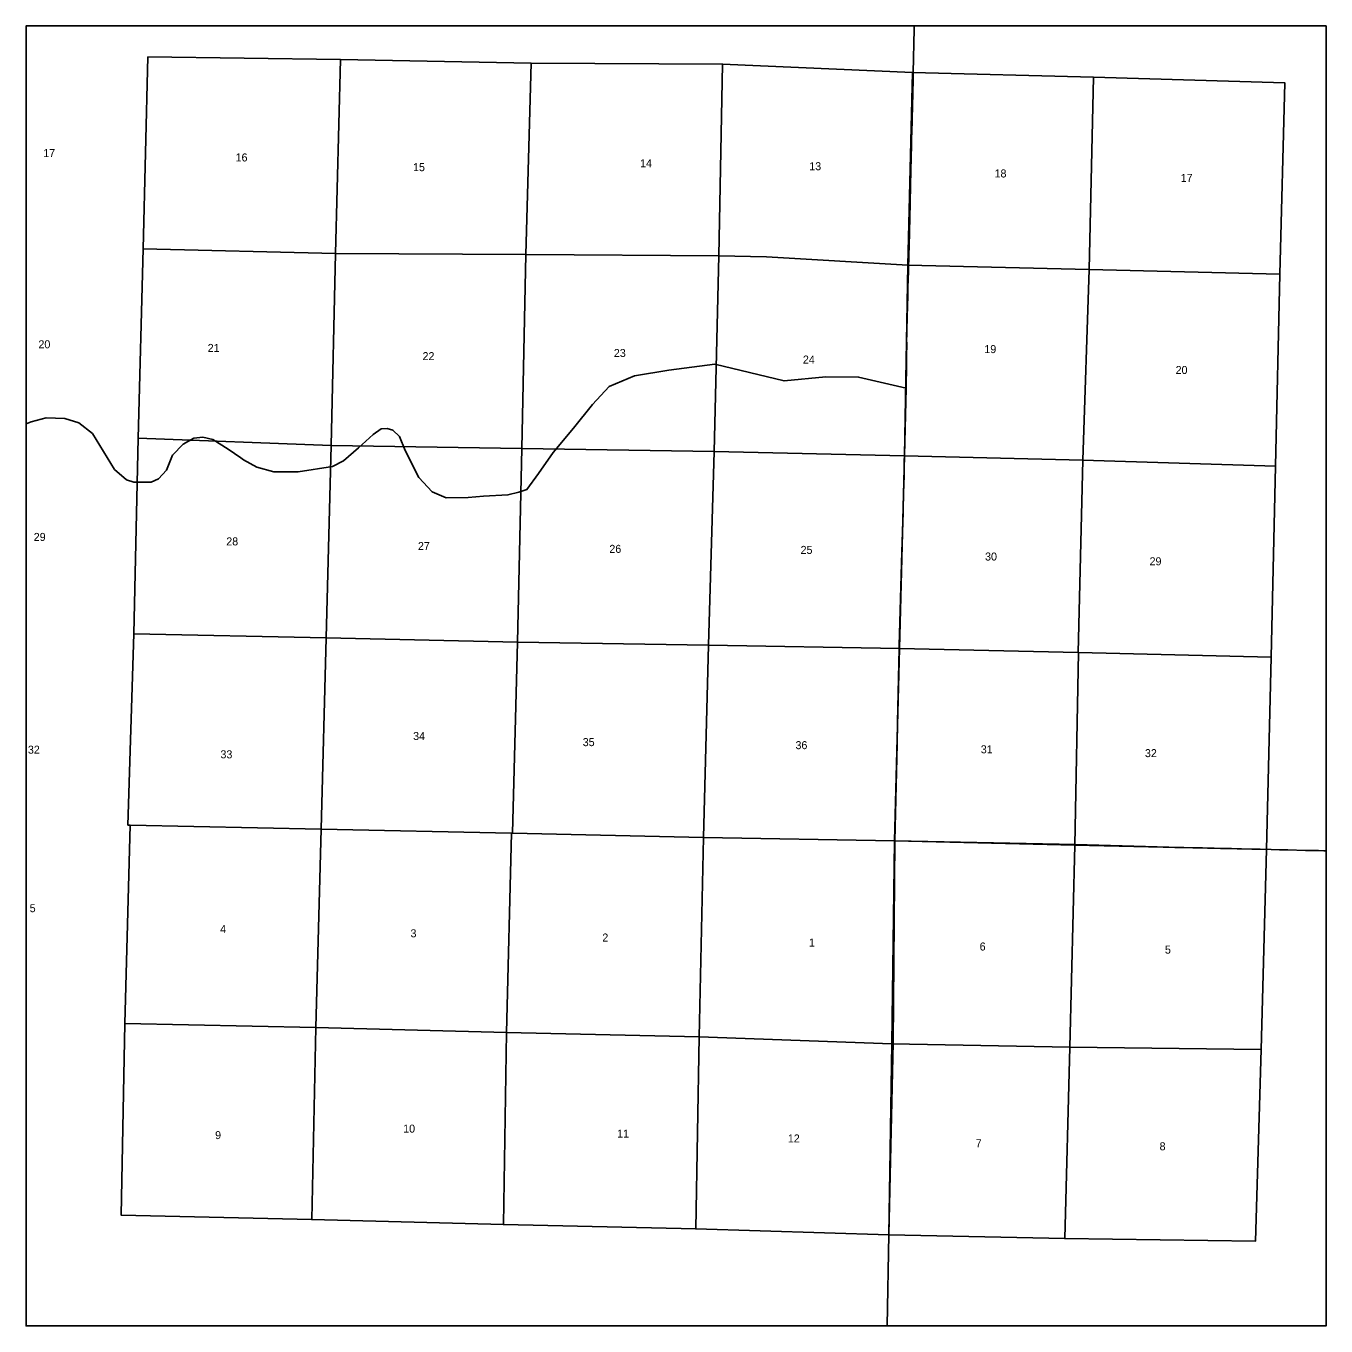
# Model space of a CAD drawing. Extents: x -483 to 680, y 0 to 440.
# Drawn here: x -395.42 to -388.62, y 271.57 to 278.37 of the extents above; entities that cross this region are included whole.
import ezdxf

# ---------------------------------------------------------------- set-up
doc = ezdxf.new("R2010")
doc.units = 0
doc.layers.add('GM_X_Section', color=7, linetype='Continuous')
doc.layers.add('GM_X_Section_Text', color=7, linetype='Continuous')

msp = doc.modelspace()

# ---------------------------------------------------------------- linework, layer by layer
at = {"layer": 'GM_X_Section'}
for points in [[(-394.782, 278.2055), (-393.775, 278.1914), (-393.8002, 277.1762), (-394.8063, 277.2013)], [(-393.775, 278.1914), (-392.7782, 278.173), (-392.8051, 277.1722), (-393.8002, 277.1762)], [(-392.7782, 278.173), (-391.7758, 278.1679), (-391.7952, 277.1651), (-392.8051, 277.1722)], [(-391.7758, 278.1679), (-390.7819, 278.1232), (-390.8079, 277.116), (-391.546, 277.1593), (-391.7952, 277.1651)], [(-390.7819, 278.1232), (-389.8362, 278.0985), (-389.8594, 277.0939), (-390.8079, 277.116)], [(-389.8362, 278.0985), (-388.8351, 278.0689), (-388.8613, 277.0689), (-389.8594, 277.0939)], [(-394.8063, 277.2013), (-393.8002, 277.1762), (-393.8233, 276.1724), (-394.8329, 276.2104)], [(-393.8002, 277.1762), (-392.8051, 277.1722), (-392.8261, 276.157), (-393.8233, 276.1724)], [(-392.8051, 277.1722), (-391.7952, 277.1651), (-391.8203, 276.1412), (-392.8261, 276.157)], [(-391.7952, 277.1651), (-391.546, 277.1593), (-390.8079, 277.116), (-390.8252, 276.1185), (-391.8203, 276.1412)], [(-390.8079, 277.116), (-389.8594, 277.0939), (-389.8919, 276.0952), (-390.8252, 276.1185)], [(-389.8594, 277.0939), (-388.8613, 277.0689), (-388.8841, 276.0644), (-389.8919, 276.0952)], [(-394.8329, 276.2104), (-393.8233, 276.1724), (-393.8502, 275.1667), (-394.8563, 275.188)], [(-393.8233, 276.1724), (-392.8261, 276.157), (-392.8487, 275.1444), (-393.8502, 275.1667)], [(-392.8261, 276.157), (-391.8203, 276.1412), (-391.8493, 275.1284), (-392.8487, 275.1444)], [(-391.8203, 276.1412), (-390.8252, 276.1185), (-390.8511, 275.111), (-391.8493, 275.1284)], [(-390.8252, 276.1185), (-389.8919, 276.0952), (-389.9167, 275.0896), (-390.8511, 275.111)], [(-389.8919, 276.0952), (-388.8841, 276.0644), (-388.9069, 275.0647), (-389.914, 275.0895), (-389.9167, 275.0896)], [(-394.8563, 275.188), (-393.8502, 275.1667), (-393.8766, 274.1663), (-394.8748, 274.187), (-394.8869, 274.1873)], [(-393.8502, 275.1667), (-392.8487, 275.1444), (-392.8754, 274.1452), (-392.8811, 274.1449), (-393.8766, 274.1663)], [(-392.8487, 275.1444), (-391.8493, 275.1284), (-391.8756, 274.1216), (-392.8754, 274.1452)], [(-391.8493, 275.1284), (-390.8511, 275.111), (-390.8762, 274.1046), (-391.8756, 274.1216)], [(-390.8511, 275.111), (-389.9167, 275.0896), (-389.914, 275.0895), (-389.9342, 274.0826), (-390.8762, 274.1046)], [(-389.914, 275.0895), (-388.9069, 275.0647), (-388.9304, 274.0602), (-389.9342, 274.0826)], [(-394.8748, 274.187), (-393.8766, 274.1663), (-393.9036, 273.1275), (-394.9025, 273.1486)], [(-393.8766, 274.1663), (-392.8811, 274.1449), (-392.9059, 273.1018), (-393.9036, 273.1275)], [(-392.8811, 274.1449), (-392.8754, 274.1452), (-391.8756, 274.1216), (-391.8981, 273.0802), (-392.9059, 273.1018)], [(-391.8756, 274.1216), (-390.8762, 274.1046), (-390.8908, 273.0436), (-391.8981, 273.0802)], [(-390.8762, 274.1046), (-389.9342, 274.0826), (-389.9605, 273.0249), (-390.8908, 273.0436)], [(-388.9304, 274.0602), (-388.9595, 273.0134), (-389.9605, 273.0249), (-389.9342, 274.0826)], [(-393.9036, 273.1275), (-393.9252, 272.1233), (-394.9222, 272.1474), (-394.9025, 273.1486)], [(-392.9059, 273.1018), (-392.9223, 272.0975), (-393.9252, 272.1233), (-393.9036, 273.1275)], [(-392.9059, 273.1018), (-391.8981, 273.0802), (-391.9168, 272.0748), (-392.9223, 272.0975)], [(-391.8981, 273.0802), (-390.8908, 273.0436), (-390.9067, 272.0446), (-391.9168, 272.0748)], [(-390.8908, 273.0436), (-389.9605, 273.0249), (-389.9863, 272.0242), (-390.9067, 272.0446)], [(-389.9605, 273.0249), (-388.9595, 273.0134), (-388.9881, 272.0109), (-389.9863, 272.0242)]]:
    msp.add_lwpolyline(points, close=True, dxfattribs=at)
at = {"layer": 'GM_X_Section_Text'}
for points in [[(-390.7732, 278.367), (-395.4198, 278.367), (-395.4198, 276.2868), (-395.3923, 276.2971), (-395.3141, 276.3178), (-395.2175, 276.3133), (-395.144, 276.2915), (-395.0715, 276.2352), (-394.9564, 276.0479), (-394.8942, 275.9939), (-394.8563, 275.9801), (-394.7649, 275.981), (-394.727, 275.9983), (-394.6845, 276.0443), (-394.6535, 276.1214), (-394.5984, 276.1789), (-394.542, 276.2112), (-394.4949, 276.2158), (-394.442, 276.2032), (-394.3615, 276.1527), (-394.2965, 276.1073), (-394.282, 276.0973), (-394.212, 276.0585), (-394.1234, 276.0345), (-393.9958, 276.0357), (-393.8165, 276.0635), (-393.759, 276.0923), (-393.6802, 276.1604), (-393.6044, 276.2294), (-393.5619, 276.2605), (-393.5309, 276.2617), (-393.501, 276.2525), (-393.4653, 276.2204), (-393.4365, 276.1468), (-393.3651, 276.0054), (-393.2949, 275.9307), (-393.2213, 275.8986), (-393.1075, 275.8999), (-393.0259, 275.908), (-392.8994, 275.9138), (-392.8412, 275.9278), (-392.7994, 275.9427), (-392.7385, 276.0267), (-392.6627, 276.136), (-392.5555, 276.263), (-392.4567, 276.3873), (-392.3694, 276.4817), (-392.2361, 276.537), (-392.0579, 276.5659), (-391.8168, 276.5986), (-391.4548, 276.5106), (-391.2363, 276.5326), (-391.065, 276.5304), (-390.8157, 276.4729), (-390.8138, 276.597), (-390.8138, 276.6176), (-390.8135, 276.643), (-390.8133, 276.6622), (-390.8131, 276.6815), (-390.8131, 276.6861), (-390.8131, 276.7038), (-390.8133, 276.7243), (-390.813, 276.751), (-390.8126, 276.7696), (-390.8121, 276.7895), (-390.8109, 276.828), (-390.8105, 276.8382), (-390.8099, 276.8528), (-390.8088, 276.8945), (-390.8081, 276.9181), (-390.8076, 276.9379), (-390.8072, 276.9559), (-390.807, 276.9678), (-390.8068, 276.9781), (-390.8063, 276.9979), (-390.805, 277.0438), (-390.8049, 277.049), (-390.8043, 277.0736), (-390.804, 277.0851), (-390.8034, 277.1037), (-390.8031, 277.1176), (-390.8025, 277.1418), (-390.8021, 277.1582), (-390.802, 277.1586), (-390.8014, 277.1803), (-390.8005, 277.2064), (-390.7997, 277.2368), (-390.7988, 277.2691), (-390.7978, 277.3131), (-390.7973, 277.3423), (-390.7974, 277.3556), (-390.7969, 277.3765), (-390.7958, 277.4295), (-390.7958, 277.4306), (-390.7951, 277.4511), (-390.7945, 277.4753), (-390.7939, 277.4995), (-390.7931, 277.5356), (-390.7928, 277.5592), (-390.7921, 277.5841), (-390.7913, 277.6114), (-390.7909, 277.6264), (-390.7902, 277.6624), (-390.7894, 277.6916), (-390.7884, 277.729), (-390.7876, 277.7714), (-390.7862, 277.8227), (-390.7849, 277.865), (-390.7843, 277.8845), (-390.7841, 277.8919), (-390.7839, 277.9016), (-390.7832, 277.9263), (-390.7829, 277.9356), (-390.7826, 277.958), (-390.7814, 278.0034), (-390.7808, 278.0265), (-390.7799, 278.0749), (-390.7789, 278.1213), (-390.7788, 278.1247), (-390.7771, 278.1975), (-390.7751, 278.2771), (-390.7737, 278.3492)], [(-388.6198, 274.0523), (-388.6198, 278.367), (-390.7732, 278.367), (-390.7737, 278.3492), (-390.7751, 278.2771), (-390.7771, 278.1975), (-390.7788, 278.1247), (-390.7789, 278.1213), (-390.7799, 278.0749), (-390.7808, 278.0265), (-390.7814, 278.0034), (-390.7826, 277.958), (-390.7829, 277.9356), (-390.7832, 277.9263), (-390.7839, 277.9016), (-390.7841, 277.8919), (-390.7843, 277.8845), (-390.7849, 277.865), (-390.7862, 277.8227), (-390.7876, 277.7714), (-390.7884, 277.729), (-390.7894, 277.6916), (-390.7902, 277.6624), (-390.7909, 277.6264), (-390.7913, 277.6114), (-390.7921, 277.5841), (-390.7928, 277.5592), (-390.7931, 277.5356), (-390.7939, 277.4995), (-390.7945, 277.4753), (-390.7951, 277.4511), (-390.7958, 277.4306), (-390.7958, 277.4295), (-390.7969, 277.3765), (-390.7974, 277.3556), (-390.7973, 277.3423), (-390.7978, 277.3131), (-390.7988, 277.2691), (-390.7997, 277.2368), (-390.8005, 277.2064), (-390.8014, 277.1803), (-390.802, 277.1586), (-390.8021, 277.1582), (-390.8025, 277.1418), (-390.8031, 277.1176), (-390.8034, 277.1037), (-390.804, 277.0851), (-390.8043, 277.0736), (-390.8049, 277.049), (-390.805, 277.0438), (-390.8063, 276.9979), (-390.8068, 276.9781), (-390.807, 276.9678), (-390.8072, 276.9559), (-390.8076, 276.9379), (-390.8081, 276.9181), (-390.8088, 276.8945), (-390.8099, 276.8528), (-390.8105, 276.8382), (-390.8109, 276.828), (-390.8121, 276.7895), (-390.8126, 276.7696), (-390.813, 276.751), (-390.8133, 276.7243), (-390.8131, 276.7038), (-390.8131, 276.6861), (-390.8131, 276.6815), (-390.8133, 276.6622), (-390.8135, 276.643), (-390.8138, 276.6176), (-390.8138, 276.597), (-390.8157, 276.4729), (-390.8249, 276.121), (-390.8256, 276.0925), (-390.826, 276.0764), (-390.8264, 276.0491), (-390.8269, 276.023), (-390.8271, 276.0159), (-390.8293, 275.9238), (-390.8301, 275.8925), (-390.8308, 275.8695), (-390.8321, 275.823), (-390.8379, 275.6172), (-390.8518, 275.1259), (-390.8518, 275.1249), (-390.8518, 275.11), (-390.861, 274.7231), (-390.8637, 274.6104), (-390.8757, 274.1044), (-389.9296, 274.0853), (-389.4417, 274.0723), (-389.4098, 274.0707), (-389.4043, 274.0706), (-389.3628, 274.0699), (-389.2994, 274.0685), (-389.2664, 274.0675), (-389.2043, 274.0664), (-389.1713, 274.0654), (-389.1378, 274.0645), (-389.1135, 274.0639), (-389.0619, 274.0627), (-388.965, 274.0607), (-388.9072, 274.059), (-388.8637, 274.0578), (-388.8195, 274.0569), (-388.7269, 274.0549), (-388.6585, 274.0534), (-388.6312, 274.0525)], [(-395.4198, 276.2868), (-395.4198, 271.567), (-390.915, 271.567), (-390.907, 272.0456), (-390.8845, 273.0503), (-390.8757, 274.1044), (-390.8637, 274.6104), (-390.861, 274.7231), (-390.8518, 275.11), (-390.8518, 275.1249), (-390.8518, 275.1259), (-390.8379, 275.6172), (-390.8321, 275.823), (-390.8308, 275.8695), (-390.8301, 275.8925), (-390.8293, 275.9238), (-390.8271, 276.0159), (-390.8269, 276.023), (-390.8264, 276.0491), (-390.826, 276.0764), (-390.8256, 276.0925), (-390.8249, 276.121), (-390.8157, 276.4729), (-391.065, 276.5304), (-391.2363, 276.5326), (-391.4548, 276.5106), (-391.8168, 276.5986), (-392.0579, 276.5659), (-392.2361, 276.537), (-392.3694, 276.4817), (-392.4567, 276.3873), (-392.5555, 276.263), (-392.6627, 276.136), (-392.7385, 276.0267), (-392.7994, 275.9427), (-392.8412, 275.9278), (-392.8994, 275.9138), (-393.0259, 275.908), (-393.1075, 275.8999), (-393.2213, 275.8986), (-393.2949, 275.9307), (-393.3651, 276.0054), (-393.4365, 276.1468), (-393.4653, 276.2204), (-393.501, 276.2525), (-393.5309, 276.2617), (-393.5619, 276.2605), (-393.6044, 276.2294), (-393.6802, 276.1604), (-393.759, 276.0923), (-393.8165, 276.0635), (-393.9958, 276.0357), (-394.1234, 276.0345), (-394.212, 276.0585), (-394.282, 276.0973), (-394.2965, 276.1073), (-394.3615, 276.1527), (-394.442, 276.2032), (-394.4949, 276.2158), (-394.542, 276.2112), (-394.5984, 276.1789), (-394.6535, 276.1214), (-394.6845, 276.0443), (-394.727, 275.9983), (-394.7649, 275.981), (-394.8563, 275.9801), (-394.8942, 275.9939), (-394.9564, 276.0479), (-395.0715, 276.2352), (-395.144, 276.2915), (-395.2175, 276.3133), (-395.3141, 276.3178), (-395.3923, 276.2971)], [(-390.915, 271.567), (-388.6198, 271.567), (-388.6198, 274.0523), (-388.6312, 274.0525), (-388.6585, 274.0534), (-388.7269, 274.0549), (-388.8195, 274.0569), (-388.8637, 274.0578), (-388.9072, 274.059), (-388.965, 274.0607), (-389.0619, 274.0627), (-389.1135, 274.0639), (-389.1378, 274.0645), (-389.1713, 274.0654), (-389.2043, 274.0664), (-389.2664, 274.0675), (-389.2994, 274.0685), (-389.3628, 274.0699), (-389.4043, 274.0706), (-389.4098, 274.0707), (-389.4417, 274.0723), (-389.9296, 274.0853), (-390.8757, 274.1044), (-390.8845, 273.0503), (-390.907, 272.0456)]]:
    msp.add_lwpolyline(points, close=True, dxfattribs=at)

# ---------------------------------------------------------------- texts
for s, height, p in [('17', 0.04186, (-395.3298, 277.6811)), ('16', 0.04186, (-394.3235, 277.6585)), ('15', 0.04186, (-393.3952, 277.6077)), ('14', 0.04186, (-392.2077, 277.6279)), ('13', 0.04186, (-391.3227, 277.6126)), ('18', 0.04186, (-390.3535, 277.5747)), ('17', 0.04186, (-389.3798, 277.5515)), ('20', 0.04186, (-395.3548, 276.681)), ('21', 0.04186, (-394.4694, 276.6621)), ('19', 0.04186, (-390.4069, 276.656)), ('22', 0.04186, (-393.3456, 276.6192)), ('23', 0.04186, (-392.3448, 276.6356)), ('24', 0.04186, (-391.356, 276.6013)), ('20', 0.04186, (-389.4065, 276.5468)), ('29', 0.04186, (-395.3794, 275.6735)), ('28', 0.04186, (-394.3723, 275.6501)), ('27', 0.04186, (-393.3698, 275.626)), ('26', 0.04186, (-392.3685, 275.611)), ('25', 0.04186, (-391.3681, 275.6056)), ('30', 0.04186, (-390.4031, 275.571)), ('29', 0.04186, (-389.5427, 275.546)), ('34', 0.04186, (-393.3948, 274.6322)), ('32', 0.04186, (-395.4098, 274.5606)), ('35', 0.04186, (-392.5077, 274.6001)), ('36', 0.04186, (-391.3948, 274.5843)), ('31', 0.04186, (-390.4256, 274.5626)), ('32', 0.04186, (-389.5669, 274.5426)), ('33', 0.04186, (-394.4027, 274.5364)), ('5', 0.0419, (-395.4006, 273.7315)), ('4', 0.0419, (-394.4044, 273.6221)), ('3', 0.0419, (-393.4085, 273.6001)), ('2', 0.0419, (-392.4052, 273.578)), ('1', 0.0419, (-391.3248, 273.5518)), ('6', 0.0419, (-390.4315, 273.531)), ('5', 0.0419, (-389.4623, 273.5148)), ('10', 0.04186, (-393.4469, 272.5785)), ('9', 0.0419, (-394.4306, 272.5447)), ('11', 0.04186, (-392.3277, 272.5526)), ('12', 0.04186, (-391.4348, 272.5271)), ('7', 0.0419, (-390.4519, 272.5023)), ('8', 0.0419, (-389.4902, 272.486))]:
    msp.add_text(s, height=height, rotation=0.00001, dxfattribs=at).set_placement(p)

doc.saveas('drawing.dxf')
